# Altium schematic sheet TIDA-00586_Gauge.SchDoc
size 431 x 279 mm; Date: Not shown in title block; ApprovedBy: Not shown in title block; CheckedBy: Not shown in title block; Author: Gordon Varney; CompanyName: Not shown in title block; DrawnBy: Gordon Varney; Engineer: Gordon Varney; Organization: Not shown in title block; Address1: Not shown in title block; Address2: Not shown in title block; Address3: Not shown in title block; Address4: Not shown in title block; DocumentNumber: 1; Revision: E1; SheetNumber: 1; SheetTotal: 1; PageSetup: Record=PageOptions¦CenterHorizontal=True¦CenterVertical=True¦PrintScale=1.00¦XCorrection=1.00¦YCorrection=1.00¦PrintKind=0¦BorderSize=5000000¦LeftOffset=0¦BottomOffset=0¦Orientation=2¦PaperLength=1000¦PaperWidth=1000¦Scale=100¦PaperSource=15¦PrintQuality=600¦MediaType=1¦DitherType=10¦PaperKind=Letter¦PrintScaleMode=1
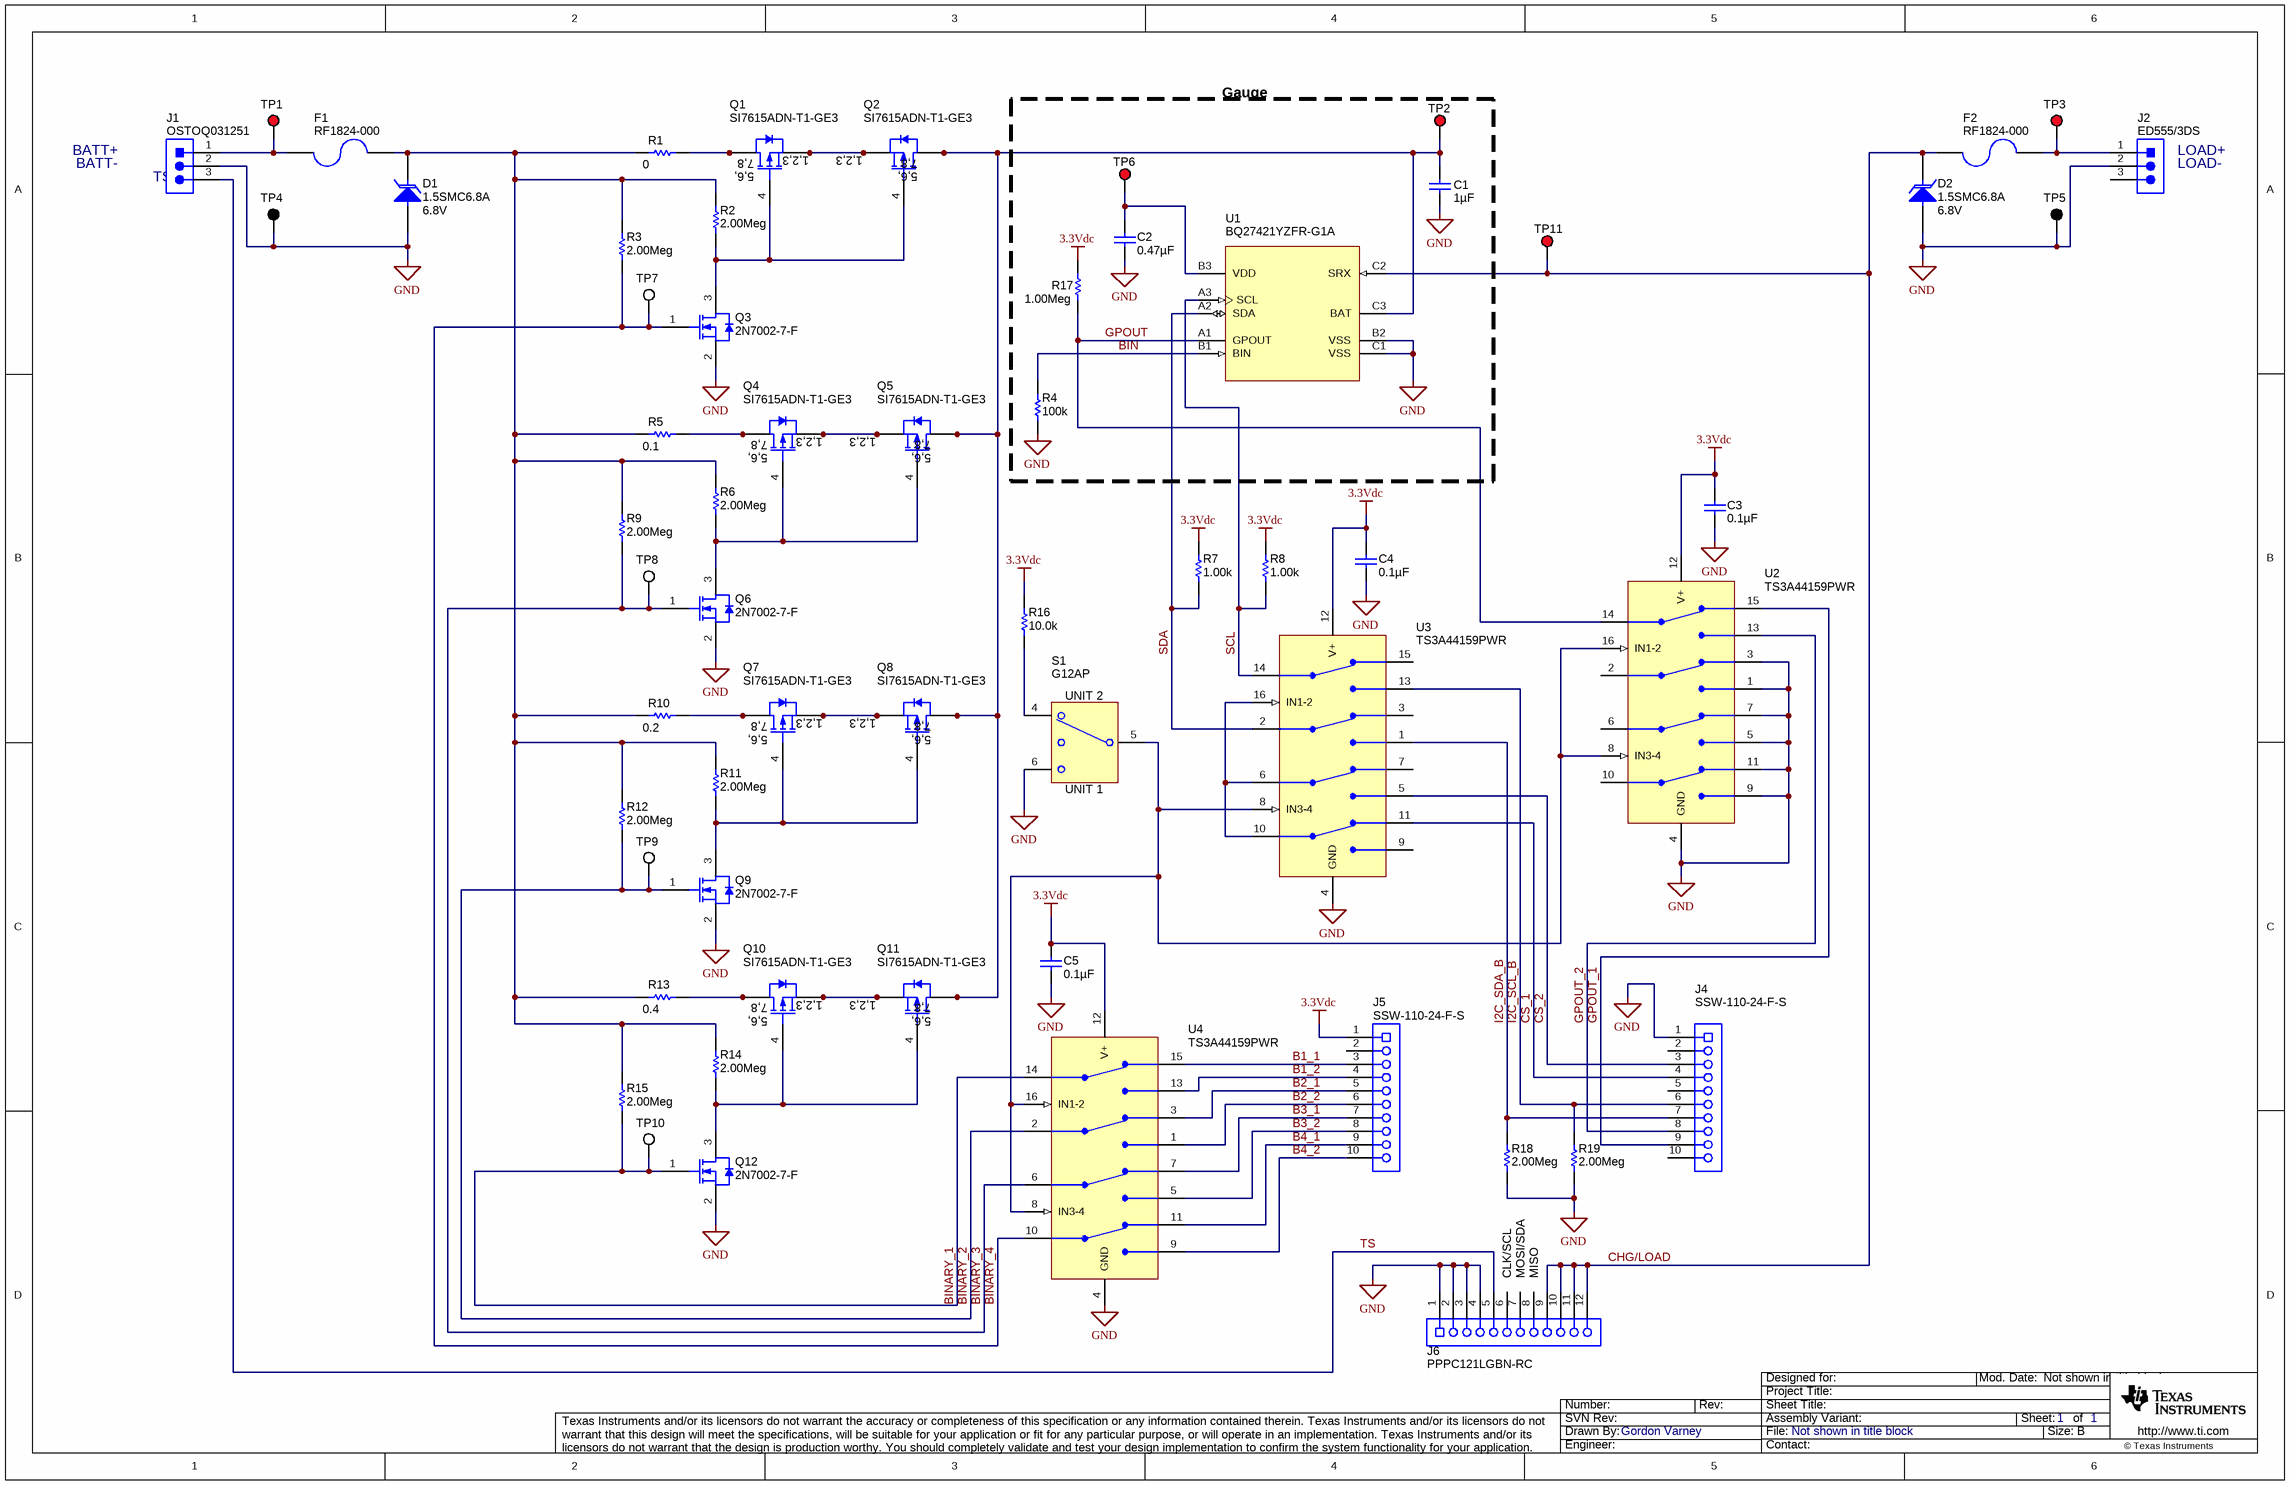
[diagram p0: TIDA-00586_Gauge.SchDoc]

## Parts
C1  ValueDisplayed: 1µF  [0402]  (hidden comment: GRM155R61A105KE15D)
C2  ValueDisplayed: 0.47µF  [0402]  (hidden comment: GRM155R60J474KE19D)
C3  ValueDisplayed: 0.1µF  [0603]  (hidden comment: C0603C104K3RACTU)
C4  ValueDisplayed: 0.1µF  [0603]  (hidden comment: C0603C104K3RACTU)
C5  ValueDisplayed: 0.1µF  [0603]  (hidden comment: C0603C104K3RACTU)
D1  1.5SMC6.8A  value 6.8V  [SMC]
D2  1.5SMC6.8A  value 6.8V  [SMC]
F1  RF1824-000  [FUSE_LR2]
F2  RF1824-000  [FUSE_LR2]
J1  OSTOQ031251  [On-Shore_OSTOQ031251]
J2  ED555/3DS  [TERM_BLK_ED555-3DS]
J4  SSW-110-24-F-S  [CONN_SSW-110-23-F-S]
J5  SSW-110-24-F-S  [CONN_SSW-110-23-F-S]
J6  PPPC121LGBN-RC  [SULLINS_PPPC121LGBN-RC]
Q1  SI7615ADN-T1-GE3  [PowerPAK_1212-8]
Q2  SI7615ADN-T1-GE3  [PowerPAK_1212-8]
Q3  2N7002-7-F  [SOT-23]
Q4  SI7615ADN-T1-GE3  [PowerPAK_1212-8]
Q5  SI7615ADN-T1-GE3  [PowerPAK_1212-8]
Q6  2N7002-7-F  [SOT-23]
Q7  SI7615ADN-T1-GE3  [PowerPAK_1212-8]
Q8  SI7615ADN-T1-GE3  [PowerPAK_1212-8]
Q9  2N7002-7-F  [SOT-23]
Q10  SI7615ADN-T1-GE3  [PowerPAK_1212-8]
Q11  SI7615ADN-T1-GE3  [PowerPAK_1212-8]
Q12  2N7002-7-F  [SOT-23]
R1  value 0  [1206]  (hidden comment: CRCW12060000Z0EA)
R2  value 2.00Meg  [0603]  (hidden comment: CRCW06032M00FKEA)
R3  value 2.00Meg  [0603]  (hidden comment: CRCW06032M00FKEA)
R4  value 100k  [0603]  (hidden comment: CRCW0603100KFKEA)
R5  value 0.1  [2010M]  (hidden comment: CSRN2010FKR100)
R6  value 2.00Meg  [0603]  (hidden comment: CRCW06032M00FKEA)
R7  value 1.00k  [0603]  (hidden comment: CRCW06031K00FKEA)
R8  value 1.00k  [0603]  (hidden comment: CRCW06031K00FKEA)
R9  value 2.00Meg  [0603]  (hidden comment: CRCW06032M00FKEA)
R10  value 0.2  [2010M]  (hidden comment: CSRN2010FKR200)
R11  value 2.00Meg  [0603]  (hidden comment: CRCW06032M00FKEA)
R12  value 2.00Meg  [0603]  (hidden comment: CRCW06032M00FKEA)
R13  value 0.4  [2010M]  (hidden comment: CSRN2010FKR400)
R14  value 2.00Meg  [0603]  (hidden comment: CRCW06032M00FKEA)
R15  value 2.00Meg  [0603]  (hidden comment: CRCW06032M00FKEA)
R16  value 10.0k  [0603]  (hidden comment: CRCW060310K0FKEA)
R17  value 1.00Meg  [0603]  (hidden comment: CRCW06031M00FKEA)
R18  value 2.00Meg  [0603]  (hidden comment: CRCW06032M00FKEA)
R19  value 2.00Meg  [0603]  (hidden comment: CRCW06032M00FKEA)
S1  G12AP  [SW_G1xAP]
TP1  5000  [Keystone5000]  (value not drawn)
TP2  5000  [Keystone5000]  (value not drawn)
TP3  5000  [Keystone5000]  (value not drawn)
TP4  5001  [Keystone5001]  (value not drawn)
TP5  5001  [Keystone5001]  (value not drawn)
TP6  5000  [Keystone5000]  (value not drawn)
TP7  5002  [Keystone5002]  (value not drawn)
TP8  5002  [Keystone5002]  (value not drawn)
TP9  5002  [Keystone5002]  (value not drawn)
TP10  5002  [Keystone5002]  (value not drawn)
TP11  5000  [Keystone5000]  (value not drawn)
U1  BQ27421YZFR-G1A  [YZF0009AKAL]
U2  TS3A44159PWR  [PW0016A_N]
U3  TS3A44159PWR  [PW0016A_N]
U4  TS3A44159PWR  [PW0016A_N]

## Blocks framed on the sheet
Gauge: C1 C2 R4 R17 TP2 TP6 U1

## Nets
3.3Vdc: C3.1 C4.1 C5.1 J5.1 R7.2 R8.2 R16.2 R17.2 U2.12(V+) U3.12(V+) U4.12(V+)
GND: C1.2 C2.2 C3.2 C4.2 C5.2 D1.2(A) D2.2(A) J1.2 J2.2 J4.1 J6.1 J6.2 J6.3 J6.4 Q3.2(S) Q6.2(S) Q9.2(S) Q12.2(S) R4.1 R18.1 R19.1 S1.6 TP4.1 TP5.1 U1.B2(VSS) U1.C1(VSS) U2.1(NO2) U2.3(NC2) U2.4(GND) U2.5(NO3) U2.7(NC3) U2.9(NO4) U2.11(NC4) U3.4(GND) U4.4(GND)
B1_1: J5.3 U4.15(NC1)
B1_2: J5.4 U4.13(NO1)
B2_1: J5.5 U4.3(NC2)
B2_2: J5.6 U4.1(NO2)
B3_1: J5.7 U4.7(NC3)
B3_2: J5.8 U4.5(NO3)
B4_1: J5.9 U4.11(NC4)
B4_2: J5.10 U4.9(NO4)
BIN: R4.2 U1.B1(BIN)
BINARY_1: Q12.1(G) R15.1 TP10.1 U4.14(COM1)
BINARY_2: Q9.1(G) R12.1 TP9.1 U4.2(COM2)
BINARY_3: Q6.1(G) R9.1 TP8.1 U4.6(COM3)
BINARY_4: Q3.1(G) R3.1 TP7.1 U4.10(COM4)
CHG/LOAD: D2.1(K) F2.1 J6.9 J6.10 J6.11 J6.12 TP11.1 U1.C2(SRX)
CS_1: J4.4 U3.11(NC4)
CS_2: J4.3 U3.5(NO3)
GPOUT: R17.1 U1.A1(GPOUT) U2.14(COM1)
GPOUT_1: J4.9 U2.15(NC1)
GPOUT_2: J4.8 U2.13(NO1)
I2C_SCL_B: J4.6 R19.2 U3.13(NO1)
I2C_SDA_B: J4.7 R18.2 U3.1(NO2)
SCL: R8.1 U1.A3(SCL) U3.14(COM1)
SDA: R7.1 U1.A2(SDA) U3.2(COM2)
TS: J1.3 J6.5
NetC1_1: C1.1 Q2.5(D) Q2.6(D) Q2.7(D) Q2.8(D) Q2.9(D) Q5.5(D) Q5.6(D) Q5.7(D) Q5.8(D) Q5.9(D) Q8.5(D) Q8.6(D) Q8.7(D) Q8.8(D) Q8.9(D) Q11.5(D) Q11.6(D) Q11.7(D) Q11.8(D) Q11.9(D) TP2.1 U1.C3(BAT)
NetC2_1: C2.1 TP6.1 U1.B3(VDD)
NetD1_1: D1.1(K) F1.2 R1.1 R2.2 R3.2 R5.1 R6.2 R9.2 R10.1 R11.2 R12.2 R13.1 R14.2 R15.2
NetF1_1: F1.1 J1.1 TP1.1
NetF2_2: F2.2 J2.1 TP3.1
NetQ1_1: Q1.1(S) Q1.2(S) Q1.3(S) Q2.1(S) Q2.2(S) Q2.3(S)
NetQ1_4: Q1.4(G) Q2.4(G) Q3.3(D) R2.1
NetQ1_5: Q1.5(D) Q1.6(D) Q1.7(D) Q1.8(D) Q1.9(D) R1.2
NetQ4_1: Q4.1(S) Q4.2(S) Q4.3(S) Q5.1(S) Q5.2(S) Q5.3(S)
NetQ4_4: Q4.4(G) Q5.4(G) Q6.3(D) R6.1
NetQ4_5: Q4.5(D) Q4.6(D) Q4.7(D) Q4.8(D) Q4.9(D) R5.2
NetQ7_1: Q7.1(S) Q7.2(S) Q7.3(S) Q8.1(S) Q8.2(S) Q8.3(S)
NetQ7_4: Q7.4(G) Q8.4(G) Q9.3(D) R11.1
NetQ7_5: Q7.5(D) Q7.6(D) Q7.7(D) Q7.8(D) Q7.9(D) R10.2
NetQ10_1: Q10.1(S) Q10.2(S) Q10.3(S) Q11.1(S) Q11.2(S) Q11.3(S)
NetQ10_4: Q10.4(G) Q11.4(G) Q12.3(D) R14.1
NetQ10_5: Q10.5(D) Q10.6(D) Q10.7(D) Q10.8(D) Q10.9(D) R13.2
NetR16_1: R16.1 S1.4
NetS1_5: S1.5(COM) U2.8(IN3-4) U2.16(IN1-2) U3.8(IN3-4) U4.8(IN3-4) U4.16(IN1-2)
NetU3_6: U3.6(COM3) U3.10(COM4) U3.16(IN1-2)

Not connected (* = marked no-connect by the designer): J2 3; J4 2 5 10; J5 2; J6 6 7 8; U2 2(COM2) 6(COM3) 10(COM4); U3 3(NC2) 7(NC3) 9(NO4) 15(NC1)

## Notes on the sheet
- (near J1) BATT+
- (near J1) BATT-
- (near J2) LOAD+
- (near J2) LOAD-
- (near J1) TS
- (near S1) UNIT 2
- (near S1) UNIT 1
- (near J6) CLK/SCL
- MOSI/SDA
- (near J6) MISO

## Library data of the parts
C1 = GRM155R61A105KE15D: CAP, CERM, 1uF, 10V, +/-10%, X5R, 0402; Manufacturer: MuRata; Polarized: N; CompType: Capacitor; U/M: EA; Cap_F: 0.000001; Tolerance_%: 10; Value1: Unknown; TaMin_C: -55; TaMax_C: 85
C2 = GRM155R60J474KE19D: CAP, CERM, 0.47uF, 6.3V, +/-10%, X5R, 0402; Manufacturer: MuRata; Polarized: N; CompType: Capacitor; U/M: EA; Cap_F: 0.00000047; Tolerance_%: 10; Value1: Unknown; VDC_V: 6.3; TaMin_C: -55; TaMax_C: 85
C3-C5 = C0603C104K3RACTU: CAP, CERM, 0.1uF, 25V, +/-10%, X7R, 0603; Manufacturer: Kemet; Polarized: N; CompType: Capacitor; U/M: EA; Cap_F: 0.0000001; Tolerance_%: 10; Value1: Unknown; VDC_V: 25; TaMin_C: -55; TaMax_C: 125
D1 D2 = 1.5SMC6.8A: Diode, TVS, Uni, 6.8V, 1500W, SMC; Manufacturer: Littelfuse; U/M: EA; Power_W: 1500; Vr_V: 6.8; RJA_CperW: 75
F1 F2 = RF1824-000: Fuse, Resettable, 1.9A, 6V, SMD; Manufacturer: TE Connectivity; SymbolCreator: a0412235; U/M: EA; VDC_V: 6; Irating_A: 1.9; Rtyp_Ohm: 0.021; MeltingTyp: 3
J1 = OSTOQ031251: Header, 3x1 3.5mm, TH; Manufacturer: On-Shore Technology; SymbolCreator: a0799628; Note: Mating Part number: OSTTJ0311530; U/M: EA
J2 = ED555/3DS: Terminal Block, 6A, 3.5mm Pitch, 3-Pos, TH; Manufacturer: On-Shore Technology; SymbolCreator: a0799628; CompType: Connector; U/M: EA
J4 J5 = SSW-110-23-F-S: Connector, Receptacle, 100mil, 10x1, Gold plated, TH; Manufacturer: Samtec; SymbolCreator: a0411947; U/M: EA
J6 = PPPC121LGBN-RC: Header, 12x1, 100mil, R/A, TH; Manufacturer: Sullins Connector Solutions; SymbolCreator: a0412235; CompType: Receptacle; U/M: EA
Q1 Q2 Q4 Q5 Q7 Q8 Q10 Q11 = SI7615ADN-T1-GE3: MOSFET, P-CH, -20V, -22.1A, PowerPAK 1212; Manufacturer: Vishay-Siliconix; Alternate Manufacturer: None; U/M: EA; ChType: P; VdsMax_V: -20; Value1: 0.006 ohm; Rdson45_Ohm: 0.006; Value2: 59 nC; QgTyp_nC: 59; Vgs_V: 12; IdsMax_A: -22.1
Q3 Q6 Q9 Q12 = 2N7002-7-F: MOSFET, N-CH, 60V, 0.17A, SOT-23; Manufacturer: Diodes Inc.; Alternate Manufacturer: None; U/M: EA; ChType: N; VdsMax_V: 60; Value1: 7.5 ohm; Rdson45_Ohm: 7.5; Value2: 223 nC; QgTyp_nC: 223; Vgs_V: 20; IdsMax_A: 0.17
R1 = CRCW12060000Z0EA: RES, 0 ohm, 5%, 0.25W, 1206; Manufacturer: Vishay-Dale; CompType: Resistor; Value_Code: 0000; Tolerance_%: 5; Power_W: 0.25; VDC_V: 200; TempCo: 200 ppm/C; EIA_Code: E24; U/M: EA
R2 R3 R6 R9 R11 R12 R14 R15 R18 R19 = CRCW06032M00FKEA: RES, 2.00Meg ohm, 1%, 0.1W, 0603; Manufacturer: Vishay-Dale; CompType: Resistor; Res_ohm: 2000000; Value_Code: 2M00; Tolerance_%: 1; Power_W: 0.1; VDC_V: 75; TempCo: 100 ppm/C; EIA_Code: E96; U/M: EA
R4 = CRCW0603100KFKEA: RES, 100k ohm, 1%, 0.1W, 0603; Manufacturer: Vishay-Dale; CompType: Resistor; Res_ohm: 100000; Tolerance_%: 1; Power_W: 0.1; VDC_V: 75; TempCo: 100 ppm/C; EIA_Code: E96; U/M: EA
R5 = CSRN2010FKR100: RES, 0.1 ohm, 1%, 1W, 2010; Manufacturer: Stackpole Electronics Inc; CompType: Resistor; Value_Code: R100; Tolerance_%: 1; TempCo: 250 ppm/C; EIA_Code: E96; U/M: EA
R7 R8 = CRCW06031K00FKEA: RES, 1.00k ohm, 1%, 0.1W, 0603; Manufacturer: Vishay-Dale; CompType: Resistor; Res_ohm: 1000; Value_Code: 1k00; Tolerance_%: 1; Power_W: 0.1; VDC_V: 75; TempCo: 100 ppm/C; EIA_Code: E96; U/M: EA
R10 = CSRN2010FKR200: RES, 0.2 ohm, 1%, 1W, 2010; Manufacturer: Stackpole Electronics Inc; CompType: Resistor; Value_Code: R200; Tolerance_%: 1; TempCo: 250 ppm/C; EIA_Code: E96; U/M: EA
R13 = CSRN2010FKR400: RES, 0.4 ohm, 1%, 1W, 2010; Manufacturer: Stackpole Electronics Inc; CompType: Resistor; Value_Code: R400; Tolerance_%: 1; TempCo: 250 ppm/C; U/M: EA
R16 = CRCW060310K0FKEA: RES, 10.0k ohm, 1%, 0.1W, 0603; Manufacturer: Vishay-Dale; CompType: Resistor; Res_ohm: 10000; Value_Code: 10k0; Tolerance_%: 1; Power_W: 0.1; VDC_V: 75; TempCo: 100 ppm/C; EIA_Code: E96; U/M: EA
R17 = CRCW06031M00FKEA: RES, 1.00Meg ohm, 1%, 0.1W, 0603; Manufacturer: Vishay-Dale; CompType: Resistor; Res_ohm: 1000000; Value_Code: 1M00; Tolerance_%: 1; Power_W: 0.1; VDC_V: 75; TempCo: 100 ppm/C; EIA_Code: E96; U/M: EA
S1 = G12AP: Switch, Toggle, SPDT 1Pos, TH; Manufacturer: NKK Switches; SymbolCreator: a0412235; VDC_V: 28; SwitchFunction: On-On; PositionCount: 1; CurrentRating_mA: 400
TP1-TP3 TP6 TP11 = 5000: Test Point, Miniature, Red, TH; Manufacturer: Keystone; CompType: Test Point Loop; U/M: EA
TP4 TP5 = 5001: Test Point, Miniature, Black, TH; Manufacturer: Keystone; CompType: Test Point Loop; U/M: EA
TP7-TP10 = 5002: Test Point, Miniature, White, TH; Manufacturer: Keystone; CompType: Test Point Loop; U/M: EA
U1 = BQ27421YZFR-G1A: System-Side Impedance Track Fuel Gauge With Integrated Sense Resistor, YZF0009AKAL; Alternate PartNumber: BQ27421YZFT-G1A; Manufacturer: Texas Instruments; SymbolCreator: Altium; CompType: IC; U/M: EA
U2-U4 = TS3A44159PWR: 0.45 ohm QUAD SPDT ANALOG SWITCH QUAD-CHANNEL 2:1 MULTIPLEXER/DEMULTIPLEXER WITH TWO CONTROLS, PW0016A; Alternate Manufacturer: None; Manufacturer: Texas Instruments; SymbolCreator: a0411947; CompType: IC; U/M: EA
